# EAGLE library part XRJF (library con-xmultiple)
RC45 schielded, without LED, with transformer, side entry PCB Jack Source: XRJF-01A-0-D2A-010(01).pdf
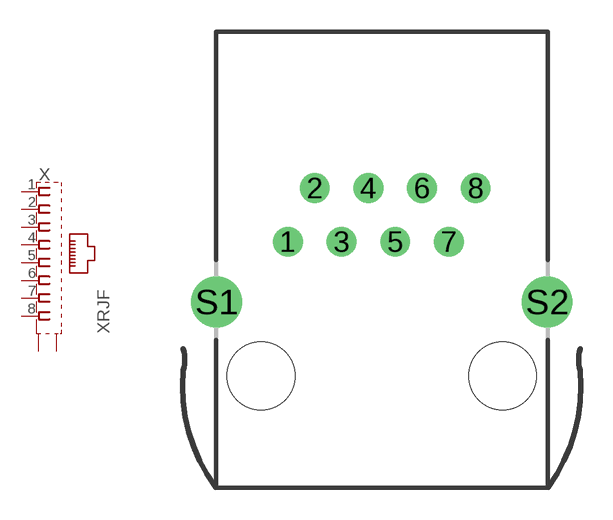
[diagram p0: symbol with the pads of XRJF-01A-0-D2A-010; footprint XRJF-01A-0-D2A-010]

Designator prefix X

## XRJF-01A-0-D2A-010, XRJF-01A-0-D22-020, XRJF-01A-0-D23-010, XRJFF-01A-0-D22-010  [XRJF-01A-0-D2A-010]
1  1  pas
2  2  pas
3  3  pas
4  4  pas
5  5  pas
6  6  pas
7  7  pas
8  8  pas
S1  S  pas
S2  S  pas

## Footprint XRJF-01A-0-D2A-010 (pad centres in mm)
RC45 without LED, schielded, with transformer, side entry PCB Jack Source: XRJF-01A-0-D2A-010(01).pdf
drill 0.9 pad 1.27 round: 1 -4.445,6.35; 2 -3.175,8.89; 3 -1.905,6.35; 4 -0.635,8.89; 5 0.635,6.35; 6 1.905,8.89; 7 3.175,6.35; 8 4.445,8.89
drill 1.6 pad 2.184 round: S1 -7.825,3.5; S2 7.825,3.5
hole 3.2 at -5.715,0
hole 3.2 at 5.715,0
